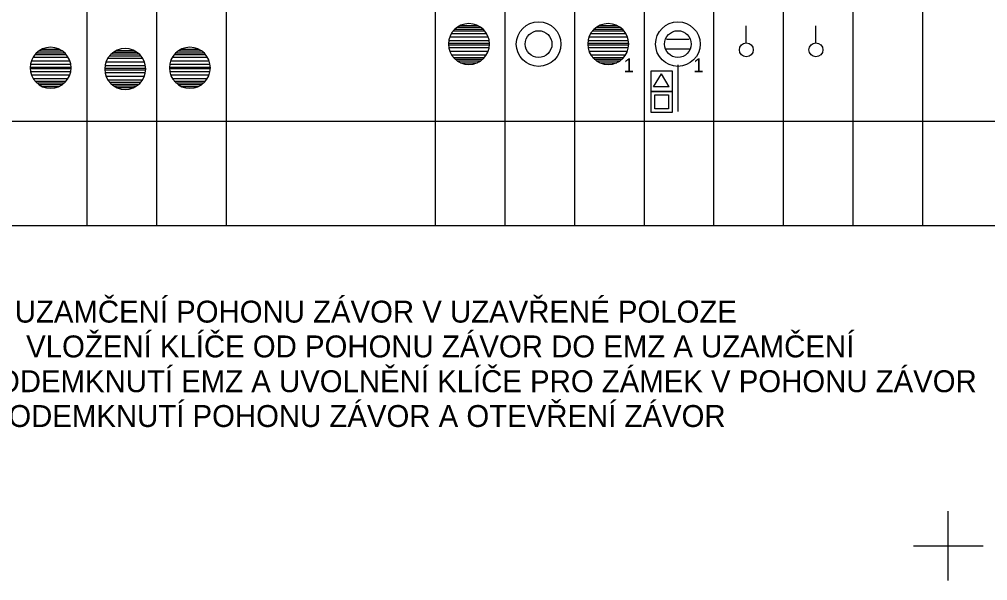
# Model space of a CAD drawing. Extents: x -28 to 822, y 61 to 665.
# Drawn here: x 53.4 to 192.5, y 60.7 to 141.4 of the extents above; entities that cross this region are included whole.
import ezdxf

# ---------------------------------------------------------------- set-up
doc = ezdxf.new("R2010")
doc.units = 0
doc.layers.add('KOLEJIŠTĚ', color=7, linetype='Continuous')
doc.layers.add('Vrstva 60', color=7, linetype='Continuous')

# ---------------------------------------------------------------- blocks, each defined once
blk = doc.blocks.new('HR3')
for radius in [2.5, 1.5]:
    blk.add_circle((0, 0), radius)
blk = doc.blocks.new('HR6')
for p, q in [((-1.96, 1.2), (1.96, 1.2)), ((-1.75, 1.49), (1.75, 1.49)), ((-1.56, 1.69), (1.56, 1.69)), ((-1.3, 1.89), (1.3, 1.89)), ((-0.95, 2.09), (0.95, 2.09)), ((-2.26, 0.4), (2.26, 0.4)), ((-2.2, 0.09), (2.2, 0.09)), ((-2.16, 0.8), (2.16, 0.8)), ((-2.26, -0.4), (2.26, -0.4)), ((-2.2, -0.09), (2.2, -0.09)), ((-2.16, -0.8), (2.16, -0.8)), ((-1.96, -1.2), (1.96, -1.2)), ((-1.75, -1.49), (1.75, -1.49)), ((-1.56, -1.69), (1.56, -1.69)), ((-1.3, -1.89), (1.3, -1.89)), ((-0.95, -2.09), (0.95, -2.09))]:
    blk.add_line(p, q)
for start, end in [(0, 180), (180, 0)]:
    blk.add_arc((0, 0), 2.3, start, end)
blk = doc.blocks.new('ZT75')
at = {"xscale": 0.8, "yscale": 0.8000000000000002}
blk.add_blockref('HR6', (0, 0), dxfattribs=at)
blk = doc.blocks.new('ZT72')
at = {"xscale": 0.8, "yscale": 0.8000000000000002}
blk.add_blockref('HR3', (0, 0), dxfattribs=at)
blk = doc.blocks.new('ZT94')
at = {"xscale": 0.6400000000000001, "yscale": 0.6400000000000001}
blk.add_blockref('HR6', (2.5, 2.5), dxfattribs=at)

msp = doc.modelspace()

# ---------------------------------------------------------------- linework, layer by layer
for p, q in [((63.12, 381.74), (63.12, 111.74)), ((73.12, 381.74), (73.12, 111.74)), ((113.12, 381.74), (113.12, 111.74)), ((123.12, 381.74), (123.12, 111.74)), ((153.12, 381.74), (153.12, 111.74)), ((163.12, 381.74), (163.12, 111.74)), ((173.12, 381.74), (173.12, 111.74)), ((183.12, 381.74), (183.12, 111.74)), ((143.12, 366.74), (143.12, 111.74)), ((83.12, 336.74), (83.12, 111.74)), ((133.12, 336.74), (133.12, 111.74)), ((157.78, 137.94), (157.78, 140.47)), ((167.78, 137.94), (167.78, 140.47)), ((146.35, 138.54), (149.62, 138.54)), ((146.3, 137.15), (149.67, 137.15)), ((144.46, 131.7), (145.62, 133.55)), ((146.73, 131.67), (145.62, 133.55)), ((148.02, 128.15), (148.02, 134.86)), ((148.02, 128.15), (148.02, 134.86)), ((146.74, 131.7), (144.46, 131.7)), ((5.07, 126.74), (293.12, 126.74)), ((5.07, 111.74), (540.62, 111.74))]:
    msp.add_line(p, q)
for points in [[(147.14, 131), (144.14, 131), (144.14, 134), (147.14, 134)], [(147.14, 128), (144.14, 128), (144.14, 131), (147.14, 131)], [(146.62, 128.54), (144.69, 128.54), (144.69, 130.54), (146.62, 130.54)]]:
    msp.add_lwpolyline(points, close=True)
for centre in [(157.81, 137), (167.81, 137)]:
    msp.add_circle(centre, 1)
at = {"layer": 'Vrstva 60'}
for p, q in [((186.81, 60.73), (186.81, 70.73)), ((181.81, 65.73), (191.81, 65.73))]:
    msp.add_line(p, q, dxfattribs=at)

# ---------------------------------------------------------------- block references
at = {"xscale": 1.2800000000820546, "yscale": 1.2800000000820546}
msp.add_blockref('HR3', (147.98, 137.83), dxfattribs=at)
at = {"layer": 'KOLEJIŠTĚ'}
for name, p, xscale, yscale in [('ZT75', (117.98, 137.83), 1.600000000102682, 1.600000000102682), ('ZT72', (127.98, 137.83), 1.600000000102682, 1.600000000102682), ('ZT75', (137.98, 137.83), 1.600000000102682, 1.600000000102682), ('ZT94', (52.91, 129.42), 2, 2), ('ZT94', (63.62, 129.25), 2, 2), ('ZT94', (72.91, 129.42), 2, 2)]:
    msp.add_blockref(name, p, dxfattribs=dict(at, xscale=xscale, yscale=yscale))

# ---------------------------------------------------------------- texts
for s, height, p in [('1', 2, (140.2, 133.78)), ('1', 2, (150.2, 133.78)), ('X     UZAMČENÍ POHONU ZÁVOR V UZAVŘENÉ POLOZE', 3.1505, (44.1, 97.81)), ('XX    VLOŽENÍ KLÍČE OD POHONU ZÁVOR DO EMZ A UZAMČENÍ ', 3.1505, (44.1, 92.81)), ('*    ODEMKNUTÍ EMZ A UVOLNĚNÍ KLÍČE PRO ZÁMEK V POHONU ZÁVOR', 3.1505, (43.89, 87.81)), ('**    ODEMKNUTÍ POHONU ZÁVOR A OTEVŘENÍ ZÁVOR', 3.1505, (43.88, 82.81))]:
    msp.add_text(s, height=height).set_placement(p)

doc.saveas('drawing.dxf')
